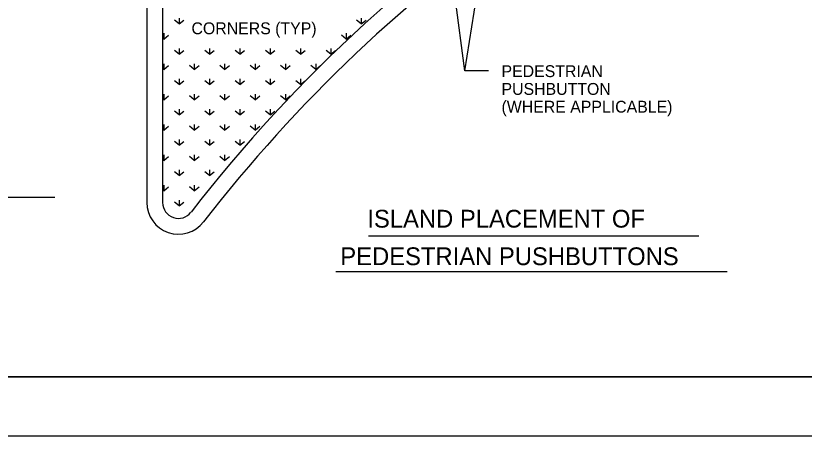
# Model space of a CAD drawing. Extents: x -344 to 940, y 22 to 1233.
# Drawn here: x 411 to 610.5, y 22.2 to 128.6 of the extents above; entities that cross this region are included whole.
import ezdxf

# ---------------------------------------------------------------- set-up
doc = ezdxf.new("R2010")
doc.units = 0
for name, color, linetype in [('1', 7, 'Continuous'), ('2', 7, 'Continuous'), ('Default', 7, 'Continuous'), ('PLT-BNDY', 7, 'Continuous')]:
    doc.layers.add(name, color=color, linetype=linetype)

msp = doc.modelspace()

# ---------------------------------------------------------------- linework, layer by layer
at = {"layer": '1'}
for p, q in [((861.86, 37.17), (75.86, 37.17)), ((75.86, 37.17), (661.86, 37.17))]:
    msp.add_line(p, q, dxfattribs=at)
at = {"layer": '2'}
for p, q in [((524.67, 114.65), (538.81, 203.71)), ((524.67, 114.65), (519.57, 152.56)), ((277.32, 82.69), (420.95, 82.69)), ((500.24, 72.87), (583.82, 72.87)), ((492.05, 63.86), (590.98, 63.86))]:
    msp.add_line(p, q, dxfattribs=at)
at = {"layer": 'Default'}
for p, q in [((444.2, 193.09), (444.2, 81.29)), ((448.2, 185.09), (448.2, 81.29)), ((452.36, 127.96), (452.36, 126.52)), ((498.44, 127.96), (498.44, 126.52)), ((452.36, 126.52), (451.16, 127.48)), ((452.36, 126.52), (453.56, 127.48)), ((498.44, 126.52), (497.24, 127.48)), ((498.44, 126.52), (499.64, 127.48)), ((448.52, 124.12), (448.52, 122.68)), ((494.6, 124.12), (494.6, 122.68)), ((448.52, 122.68), (448.2, 122.93)), ((448.52, 122.68), (449.72, 123.64)), ((494.6, 122.68), (493.4, 123.64)), ((494.6, 122.68), (495.8, 123.64)), ((452.36, 118.84), (451.16, 119.8)), ((452.36, 120.28), (452.36, 118.84)), ((452.36, 118.84), (453.56, 119.8)), ((460.04, 118.84), (458.84, 119.8)), ((460.04, 120.28), (460.04, 118.84)), ((460.04, 118.84), (461.24, 119.8)), ((467.72, 118.84), (466.52, 119.8)), ((467.72, 120.28), (467.72, 118.84)), ((467.72, 118.84), (468.92, 119.8)), ((475.4, 118.84), (474.2, 119.8)), ((475.4, 120.28), (475.4, 118.84)), ((475.4, 118.84), (476.6, 119.8)), ((483.08, 118.84), (481.88, 119.8)), ((483.08, 120.28), (483.08, 118.84)), ((483.08, 118.84), (484.28, 119.8)), ((490.76, 118.84), (489.56, 119.8)), ((490.76, 120.28), (490.76, 118.84)), ((490.76, 118.84), (491.96, 119.8)), ((448.52, 116.44), (448.52, 115)), ((448.52, 115), (449.72, 115.96)), ((456.2, 115), (455, 115.96)), ((456.2, 116.44), (456.2, 115)), ((456.2, 115), (457.4, 115.96)), ((463.88, 115), (462.68, 115.96)), ((463.88, 116.44), (463.88, 115)), ((463.88, 115), (465.08, 115.96)), ((471.56, 115), (470.36, 115.96)), ((471.56, 116.44), (471.56, 115)), ((471.56, 115), (472.76, 115.96)), ((479.24, 115), (478.04, 115.96)), ((479.24, 116.44), (479.24, 115)), ((479.24, 115), (480.44, 115.96)), ((486.92, 115), (485.72, 115.96)), ((486.92, 116.44), (486.92, 115)), ((486.92, 115), (488.12, 115.96)), ((448.52, 115), (448.2, 115.25)), ((530.67, 114.65), (524.67, 114.65)), ((452.36, 111.16), (451.16, 112.12)), ((452.36, 112.6), (452.36, 111.16)), ((452.36, 111.16), (453.56, 112.12)), ((460.04, 111.16), (458.84, 112.12)), ((460.04, 112.6), (460.04, 111.16)), ((460.04, 111.16), (461.24, 112.12)), ((467.72, 111.16), (466.52, 112.12)), ((467.72, 112.6), (467.72, 111.16)), ((467.72, 111.16), (468.92, 112.12)), ((475.4, 111.16), (474.2, 112.12)), ((475.4, 112.6), (475.4, 111.16)), ((475.4, 111.16), (476.6, 112.12)), ((483.08, 111.16), (481.88, 112.12)), ((483.08, 112.6), (483.08, 111.16)), ((483.08, 111.16), (484.28, 112.12)), ((448.52, 108.76), (448.52, 107.32)), ((448.52, 107.32), (449.72, 108.28)), ((456.2, 107.32), (455, 108.28)), ((456.2, 108.76), (456.2, 107.32)), ((456.2, 107.32), (457.4, 108.28)), ((463.88, 107.32), (462.68, 108.28)), ((463.88, 108.76), (463.88, 107.32)), ((463.88, 107.32), (465.08, 108.28)), ((471.56, 107.32), (470.36, 108.28)), ((471.56, 108.76), (471.56, 107.32)), ((471.56, 107.32), (472.76, 108.28)), ((479.24, 107.32), (478.04, 108.28)), ((479.24, 108.76), (479.24, 107.32)), ((479.24, 107.32), (480.44, 108.28)), ((448.52, 107.32), (448.2, 107.57)), ((452.36, 103.48), (451.16, 104.44)), ((452.36, 104.92), (452.36, 103.48)), ((452.36, 103.48), (453.56, 104.44)), ((460.04, 103.48), (458.84, 104.44)), ((460.04, 104.92), (460.04, 103.48)), ((460.04, 103.48), (461.24, 104.44)), ((467.72, 103.48), (466.52, 104.44)), ((467.72, 104.92), (467.72, 103.48)), ((467.72, 103.48), (468.92, 104.44)), ((475.4, 103.48), (474.2, 104.44)), ((475.4, 104.92), (475.4, 103.48)), ((475.4, 103.48), (476.6, 104.44)), ((448.52, 99.64), (448.2, 99.89)), ((448.52, 101.08), (448.52, 99.64)), ((448.52, 99.64), (449.72, 100.6)), ((456.2, 99.64), (455, 100.6)), ((456.2, 101.08), (456.2, 99.64)), ((456.2, 99.64), (457.4, 100.6)), ((463.88, 99.64), (462.68, 100.6)), ((463.88, 101.08), (463.88, 99.64)), ((463.88, 99.64), (465.08, 100.6)), ((471.56, 99.64), (470.36, 100.6)), ((471.56, 101.08), (471.56, 99.64)), ((471.56, 99.64), (472.76, 100.6)), ((452.36, 95.8), (451.16, 96.76)), ((452.36, 97.24), (452.36, 95.8)), ((452.36, 95.8), (453.56, 96.76)), ((460.04, 95.8), (458.84, 96.76)), ((460.04, 97.24), (460.04, 95.8)), ((460.04, 95.8), (461.24, 96.76)), ((467.72, 95.8), (466.52, 96.76)), ((467.72, 97.24), (467.72, 95.8)), ((467.72, 95.8), (468.92, 96.76)), ((448.52, 91.96), (448.2, 92.21)), ((448.52, 93.4), (448.52, 91.96)), ((448.52, 91.96), (449.72, 92.92)), ((456.2, 91.96), (455, 92.92)), ((456.2, 93.4), (456.2, 91.96)), ((456.2, 91.96), (457.4, 92.92)), ((463.88, 91.96), (462.68, 92.92)), ((463.88, 93.4), (463.88, 91.96)), ((463.88, 91.96), (465.08, 92.92)), ((452.36, 88.12), (451.16, 89.08)), ((452.36, 89.56), (452.36, 88.12)), ((452.36, 88.12), (453.56, 89.08)), ((460.04, 88.12), (458.84, 89.08)), ((460.04, 89.56), (460.04, 88.12)), ((460.04, 88.12), (461.24, 89.08)), ((448.52, 84.28), (448.2, 84.53)), ((448.52, 85.72), (448.52, 84.28)), ((448.52, 84.28), (449.72, 85.24)), ((456.2, 84.28), (455, 85.24)), ((456.2, 85.72), (456.2, 84.28)), ((456.2, 84.28), (457.4, 85.24)), ((452.36, 81.88), (452.36, 80.44)), ((452.36, 80.44), (451.16, 81.4)), ((452.36, 80.44), (453.56, 81.4))]:
    msp.add_line(p, q, dxfattribs=at)
for centre, radius, start, end in [((753.46, -151.64), 376.8, 122.5261, 142.2884), ((753.46, -151.64), 372.8, 124.6158, 142.2884), ((452.2, 81.29), 8, 180, 322.2884), ((452.2, 81.29), 4, 180, 322.2884)]:
    msp.add_arc(centre, radius, start, end, dxfattribs=at)
at = {"layer": 'PLT-BNDY'}
msp.add_lwpolyline([(35.86, 616.17), (876.86, 616.17), (876.86, 22.17), (35.86, 22.17)], close=True, dxfattribs=at)

# ---------------------------------------------------------------- texts
at = {"layer": '2'}
for s, p in [('ISLAND PLACEMENT OF', (499.98, 74.96)), ('PEDESTRIAN PUSHBUTTONS', (493.14, 65.46))]:
    msp.add_text(s, height=4.5, dxfattribs=at).set_placement(p)
at = {"layer": 'Default'}
for s, p in [('CORNERS (TYP)', (455.49, 123.89)), ('PEDESTRIAN', (533.92, 113.05)), ('PUSHBUTTON', (533.92, 108.55)), ('(WHERE APPLICABLE)', (533.92, 104.05))]:
    msp.add_text(s, height=3, dxfattribs=at).set_placement(p)

doc.saveas('drawing.dxf')
